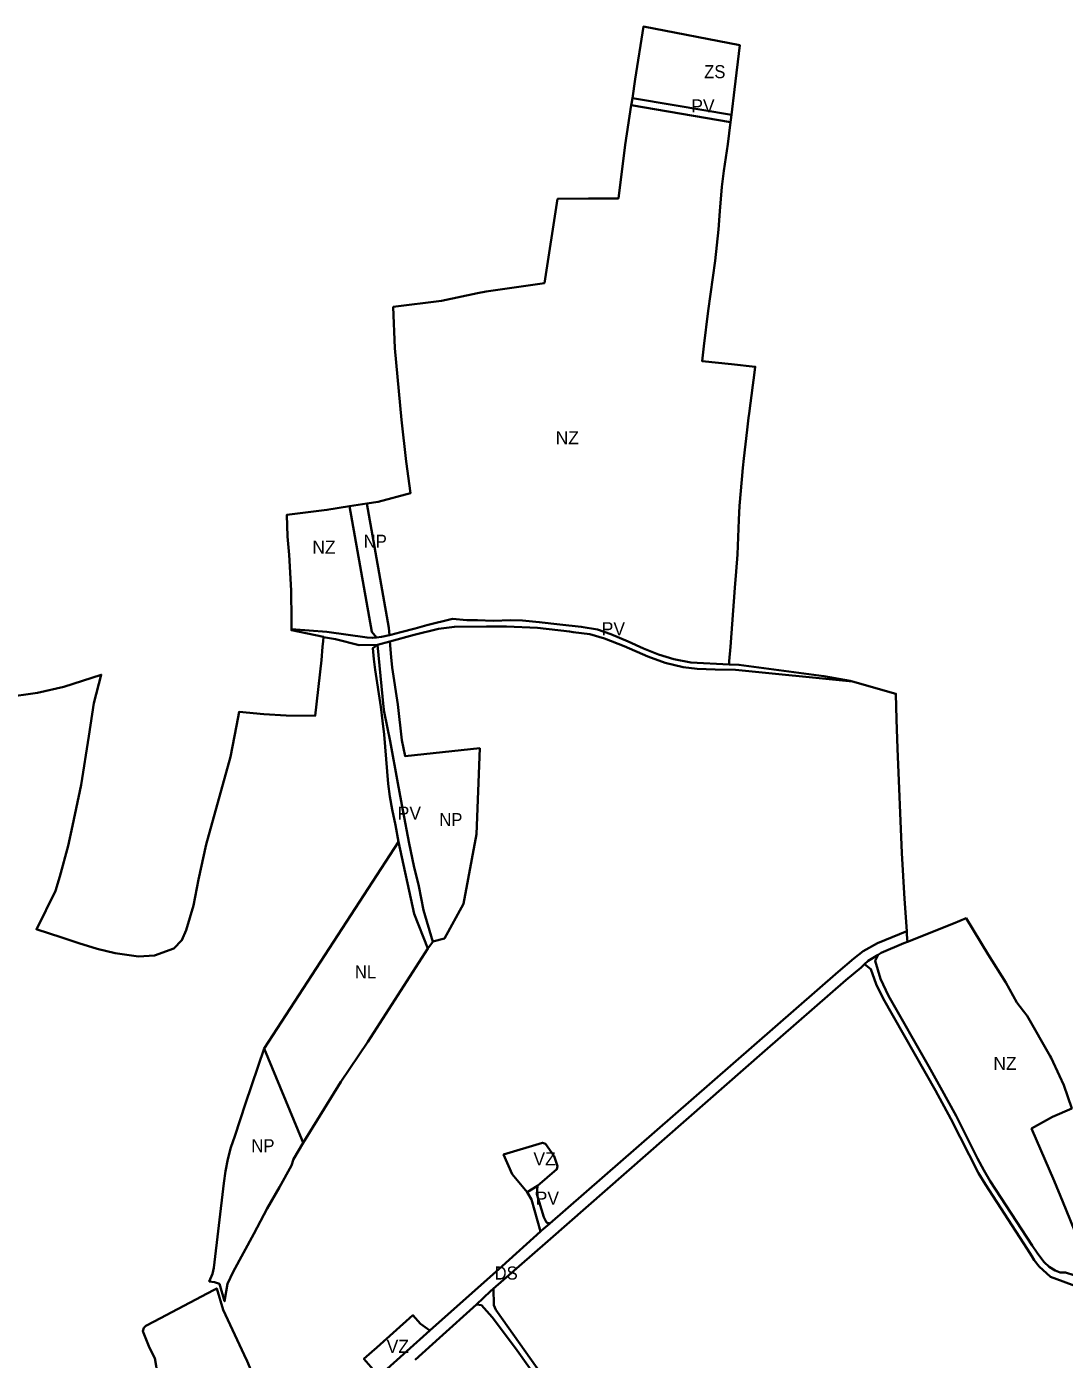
# Model space of a CAD drawing. Extents: x -650451 to -642268, y -1075216 to -1066610.
# Drawn here: x -646190 to -644999, y -1068487 to -1066957 of the extents above; entities that cross this region are included whole.
import ezdxf

# ---------------------------------------------------------------- set-up
doc = ezdxf.new("R2010")
doc.units = 0
doc.header["$LTSCALE"] = 6
doc.layers.add('1', color=7, linetype='Continuous', lineweight=35)
doc.layers.add('2', color=7, linetype='Continuous')
doc.layers.add('3', color=7, linetype='Continuous')

msp = doc.modelspace()

# ---------------------------------------------------------------- linework, layer by layer
at = {"layer": '1'}
for p, q in [((-645382.21, -1067066.58), (-645496.09, -1067047.12)), ((-645799.72, -1067504.47), (-645819.48, -1067507.57)), ((-645787.55, -1067666.46), (-645773.23, -1067662.67)), ((-645917.44, -1068129.99), (-645763.31, -1067892.76)), ((-645729.57, -1068015.25), (-645723.73, -1068007.49)), ((-645603.62, -1068287.78), (-645615.49, -1068294.75)), ((-645657.63, -1068408.53), (-645673.86, -1068423.84))]:
    msp.add_line(p, q, dxfattribs=at)
for points in [[(-645494.89, -1067039.24), (-645491.53, -1067017.12), (-645482.19, -1066956.97), (-645371.52, -1066978.24), (-645377.46, -1067029.23), (-645381.13, -1067058.07)], [(-645494.89, -1067039.24), (-645495.83, -1067045.42), (-645495.92, -1067046), (-645496.09, -1067047.12)], [(-645381.13, -1067058.07), (-645446.75, -1067047.21), (-645494.89, -1067039.24)], [(-645496.09, -1067047.12), (-645503.12, -1067092.52), (-645510.95, -1067154.14), (-645545.1, -1067154.42), (-645580.79, -1067154.71), (-645595.88, -1067251.4), (-645662.58, -1067260.94), (-645672.62, -1067263.07), (-645713.88, -1067271.8), (-645769.39, -1067278.68), (-645767.6, -1067326), (-645759.82, -1067408.4), (-645754.45, -1067456.07), (-645749.67, -1067492.54), (-645786.52, -1067502.4), (-645799.72, -1067504.47)], [(-645383.93, -1067689.29), (-645383.61, -1067685.21), (-645382.36, -1067669.07), (-645377.07, -1067601.06), (-645375.63, -1067582.48), (-645374.09, -1067562.75), (-645372.51, -1067523.27), (-645371.73, -1067507.06), (-645369.16, -1067476.7), (-645367.93, -1067463.58), (-645366.91, -1067452.72), (-645363.1, -1067419.95), (-645361.48, -1067406.06), (-645360.9, -1067401.05), (-645356.48, -1067368.37), (-645354.97, -1067357.16), (-645353.76, -1067347.31), (-645381.01, -1067344.47), (-645414.55, -1067340.98), (-645412.77, -1067323.6), (-645407.69, -1067283.25), (-645399.81, -1067225.64), (-645395.86, -1067189.95), (-645394.32, -1067168.93), (-645392.26, -1067140.66), (-645389.77, -1067122.54), (-645385.41, -1067091.78), (-645382.21, -1067066.58)], [(-645382.21, -1067066.58), (-645381.88, -1067064.01), (-645381.13, -1067058.07)], [(-645819.48, -1067507.57), (-645845.49, -1067511.66), (-645891.61, -1067517.46), (-645890.8, -1067542.09), (-645888.69, -1067563.35), (-645886.5, -1067604.41), (-645886.3, -1067638), (-645886.24, -1067648.47)], [(-645819.48, -1067507.57), (-645793.94, -1067651.61), (-645788.395, -1067658.038)], [(-645799.72, -1067504.47), (-645774.48, -1067646.99), (-645773.771, -1067655.463)], [(-645383.93, -1067689.29), (-645427.67, -1067686.98), (-645447.36, -1067682.99), (-645464.97, -1067677.86), (-645481.91, -1067670.72), (-645499.63, -1067662.69), (-645519.72, -1067654.33), (-645534.71, -1067649.04), (-645553.5, -1067645.77), (-645578.23, -1067643.18), (-645601.76, -1067640.56), (-645621.09, -1067638.61), (-645634.35, -1067638.25), (-645654.82, -1067638.96), (-645672.81, -1067638.43), (-645685.05, -1067638.32), (-645701.45, -1067636.93), (-645730.83, -1067643.84), (-645744.22, -1067647.86), (-645760.67, -1067652.05), (-645772.13, -1067655.13), (-645773.771, -1067655.463)], [(-645886.24, -1067648.47), (-645886.23, -1067649.44), (-645886.23, -1067649.94), (-645849.48, -1067657.36), (-645849.52, -1067657.86)], [(-645886.24, -1067648.47), (-645845.57, -1067651.64), (-645799.46, -1067658.29), (-645792.97, -1067658.65), (-645788.395, -1067658.038)], [(-645773.23, -1067662.67), (-645745.35, -1067655.28), (-645717.47, -1067648.33), (-645699.06, -1067645.85), (-645662.28, -1067645.47), (-645639.18, -1067645.44), (-645603.9, -1067647.11), (-645566.95, -1067651.44), (-645562.8, -1067651.97), (-645543.71, -1067654.42), (-645526.79, -1067659.39), (-645504.22, -1067668.01), (-645477.15, -1067680.1), (-645457.35, -1067687.14), (-645436.45, -1067692.2), (-645420.53, -1067694.05), (-645399.68, -1067695), (-645376.45, -1067695.27), (-645241.99, -1067708.63)], [(-645849.52, -1067657.86), (-645849.92, -1067662.49), (-645850.48, -1067668.94), (-645851.81, -1067684.35), (-645858.82, -1067747.99), (-645892.22, -1067747.76), (-645917.73, -1067746.17), (-645946.03, -1067743.35), (-645949.27, -1067759.64), (-645955.97, -1067795.26), (-645983.9, -1067895.9), (-645992.8, -1067935.9), (-645998.8, -1067965.7), (-646007, -1067994.3), (-646011.9, -1068005.55), (-646021.3, -1068015.1), (-646043.5, -1068023.3), (-646061.9, -1068024.2), (-646088.7, -1068020.6), (-646109.2, -1068015.7), (-646130.17, -1068008.93), (-646151, -1068002.21), (-646178.1, -1067993.46), (-646178.9, -1067993.2), (-646157.138, -1067949.001), (-646152.186, -1067932.667), (-646142.3, -1067897.5), (-646137.4, -1067874.3), (-646127.7, -1067827.4), (-646118.8, -1067771.3), (-646113, -1067733.4), (-646104.6, -1067701), (-646147.4, -1067714.8), (-646177.7, -1067721.6), (-646215.6, -1067727)], [(-645849.52, -1067657.86), (-645835.71, -1067660.17), (-645808.36, -1067666.89), (-645787.55, -1067666.46)], [(-645763.31, -1067892.76), (-645766.73, -1067873.61), (-645770.55, -1067855.68), (-645773.28, -1067840.65), (-645775.01, -1067826.23), (-645779.93, -1067769.7), (-645781.58, -1067753.73), (-645783.74, -1067737.82), (-645790.2, -1067695.38), (-645791.77, -1067682.92), (-645792.71, -1067670.4), (-645787.55, -1067666.46)], [(-645788.395, -1067658.038), (-645782.72, -1067657.28), (-645773.771, -1067655.463)], [(-645787.55, -1067666.46), (-645780.39, -1067737.84), (-645779.64, -1067743.41), (-645773.04, -1067777.35), (-645764.11, -1067825.26), (-645758.47, -1067856.55), (-645751.08, -1067894.5), (-645745.86, -1067920.32), (-645739.85, -1067943.75), (-645734.61, -1067971.28), (-645723.73, -1068007.49)], [(-645773.23, -1067662.67), (-645771.86, -1067680.92), (-645770.39, -1067692.63), (-645763.92, -1067735.14), (-645759.32, -1067775.89), (-645755.758, -1067794.254), (-645670.064, -1067785.335), (-645673.827, -1067884.119), (-645688.88, -1067964.087), (-645710.519, -1068003.601), (-645723.785, -1068007.069), (-645723.73, -1068007.49)], [(-645241.99, -1067708.63), (-645244.7, -1067707.86), (-645275.06, -1067702.69), (-645372.48, -1067689.42), (-645383.93, -1067689.29)], [(-645179.89, -1067995.2), (-645182.4, -1067958.11), (-645185.5, -1067905.76), (-645190.61, -1067785.41), (-645191.55, -1067752.42), (-645192.4, -1067722.74), (-645241.99, -1067708.63)], [(-645763.31, -1067892.76), (-645745.28, -1067975.27), (-645729.57, -1068015.25)], [(-644959.42, -1068409.51), (-644963.44, -1068401.84), (-644969.23, -1068390.78), (-644983.04, -1068349.19), (-645000.93, -1068306.11), (-645010.65, -1068282), (-645036.69, -1068221.92), (-645012.64, -1068208.23), (-644990.43, -1068198.75), (-644999.74, -1068171.88), (-645004.64, -1068161.3), (-645014.09, -1068140.85), (-645015.38, -1068138.59), (-645041.75, -1068092.48), (-645045.78, -1068087.19), (-645053.36, -1068077.25), (-645066.21, -1068054.16), (-645086.3, -1068021.92), (-645111.83, -1067980.38), (-645126.11, -1067986.52), (-645179.06, -1068007.39)], [(-645589.734, -1068330.849), (-645427.4, -1068189.15), (-645258.58, -1068041.8), (-645240.62, -1068026.53), (-645229.95, -1068018.28), (-645213.6, -1068009.2), (-645179.89, -1067995.2)], [(-645179.89, -1067995.2), (-645179.67, -1067998.38), (-645179.28, -1068004.08), (-645179.06, -1068007.39)], [(-645729.57, -1068015.25), (-645798.69, -1068122.17), (-645829.66, -1068168.34), (-645872.64, -1068238.08)], [(-645179.06, -1068007.39), (-645183.06, -1068008.96), (-645209.31, -1068020.07), (-645212.831, -1068022.262)], [(-645228.257, -1068033.102), (-645232.31, -1068036.91), (-645249.9, -1068051.45), (-645342.79, -1068132.81), (-645592.08, -1068351.12), (-645657.63, -1068408.53)], [(-645212.831, -1068022.262), (-645224.36, -1068029.44), (-645228.257, -1068033.102)], [(-644982.58, -1068403.83), (-645014.95, -1068392.17), (-645027.82, -1068380.21), (-645033.49, -1068372.96), (-645036.31, -1068368.47), (-645041.56, -1068359.96), (-645089.68, -1068286.16), (-645097.68, -1068273.03), (-645129.48, -1068210.55), (-645147.09, -1068178.35), (-645206.9, -1068072.73), (-645215.02, -1068056.12), (-645221, -1068038.9), (-645228.257, -1068033.102)], [(-644959.42, -1068409.51), (-644966.17, -1068403.25), (-644970.72, -1068399.33), (-644978.39, -1068393.26), (-644997.7, -1068387.1), (-645003.98, -1068387.18), (-645009.72, -1068384.69), (-645016.44, -1068380.44), (-645022.34, -1068375.11), (-645027.23, -1068368.85), (-645030.2, -1068364.48), (-645035.86, -1068356.25), (-645083.99, -1068282.08), (-645091.6, -1068269.57), (-645098.61, -1068256.33), (-645106.55, -1068240.15), (-645123.29, -1068207.28), (-645140.99, -1068174.92), (-645154.68, -1068150.75), (-645200.78, -1068069.33), (-645210.19, -1068049.9), (-645216.33, -1068029.45), (-645212.831, -1068022.262)], [(-645917.44, -1068129.99), (-645938.87, -1068193.06), (-645951.35, -1068230.61), (-645955.63, -1068243.79), (-645959.15, -1068257.17), (-645961.93, -1068270.74), (-645963.94, -1068284.44), (-645975.46, -1068381.74), (-645976.72, -1068388.53), (-645980.61, -1068397.35), (-645974.67, -1068398.28), (-645968.86, -1068400.15), (-645962.86, -1068420.15), (-645959.41, -1068400.16), (-645952.92, -1068386.53), (-645929.29, -1068342.91), (-645914.12, -1068313.54), (-645899.73, -1068289.25), (-645886.28, -1068264.22), (-645883.87, -1068256.88), (-645872.64, -1068238.08)], [(-645872.64, -1068238.08), (-645874.15, -1068234.44), (-645917.44, -1068129.99)], [(-645615.49, -1068294.75), (-645632.7, -1068274.33), (-645642.71, -1068251.69), (-645597.95, -1068238.07), (-645594.58, -1068239.29), (-645584.8, -1068253.71), (-645580.86, -1068265.06), (-645581.51, -1068268.4), (-645603.62, -1068287.78)], [(-645600.441, -1068340.017), (-645610.72, -1068303.48), (-645615.49, -1068294.75)], [(-645603.62, -1068287.78), (-645604.65, -1068297.22), (-645596.36, -1068323.47), (-645593.42, -1068329.62), (-645589.734, -1068330.849)], [(-645727.32, -1068453.86), (-645644.17, -1068379.88), (-645600.441, -1068340.017)], [(-645600.441, -1068340.017), (-645599.6, -1068339.25), (-645596.883, -1068336.974), (-645590.025, -1068331.103), (-645589.734, -1068330.849)], [(-646149.04, -1068659.6), (-646149.99, -1068658.12), (-646136.66, -1068651.17), (-646028.19, -1068584.65), (-646036.27, -1068530.56), (-646041.44, -1068494.27), (-646043.13, -1068485.53), (-646048.96, -1068473.76), (-646051.28, -1068467.73), (-646055.39, -1068458.11), (-646056.77, -1068454.35), (-646055.56, -1068450.55), (-646053.26, -1068448.37), (-646043.93, -1068443.44), (-645975.47, -1068407.25), (-645971.94, -1068405.38), (-645964.53, -1068429.83), (-645964.51, -1068429.88), (-645940.28, -1068481.66), (-645936.95, -1068488.76), (-645927.86, -1068510.76), (-645924.25, -1068530.17), (-645922.02, -1068539.96)], [(-645657.63, -1068408.53), (-645654.34, -1068405.65), (-645653.87, -1068424.71), (-645651.53, -1068430.1), (-645591.03, -1068515.22), (-645587.94, -1068519.19), (-645580.2, -1068531.93), (-645576.6, -1068540.35), (-645574.36, -1068545.66), (-645570.55, -1068560.09), (-645568.86, -1068574.89), (-645568.88, -1068579.93), (-645563.42, -1068709.35), (-645557.97, -1068838.77), (-645557.27, -1068843.66), (-645556.12, -1068850.33), (-645553.29, -1068856.55), (-645552.302, -1068859.444)], [(-645673.86, -1068423.84), (-645716.22, -1068462.08), (-645744.06, -1068487.4)], [(-645632.76, -1068904.96), (-645605.99, -1068885.11), (-645567.83, -1068857.79), (-645564.25, -1068849.99), (-645565.26, -1068844.12), (-645564.97, -1068839.07), (-645565.34, -1068825.58), (-645568.99, -1068739.04), (-645571.75, -1068677.77), (-645575.86, -1068580.22), (-645576.29, -1068575.28), (-645577.8, -1068561.45), (-645581.4, -1068548.08), (-645586.82, -1068535.33), (-645594.04, -1068523.44), (-645596.74, -1068519.27), (-645628.94, -1068473.97), (-645655.81, -1068438.19), (-645668.04, -1068424.72), (-645673.86, -1068423.84)], [(-645727.32, -1068453.86), (-645737.89, -1068446.04), (-645746.68, -1068436.15), (-645788.09, -1068473.04), (-645794.06, -1068478.36), (-645803.01, -1068486.33), (-645789.58, -1068501.42)], [(-645727.32, -1068453.86), (-645780.28, -1068501.04), (-645785.72, -1068505.75)]]:
    msp.add_lwpolyline(points, dxfattribs=at)

# ---------------------------------------------------------------- texts
at = {"layer": '2', "width": 0.95}
for s, p in [('ZS', (-645412.41, -1067016.14)), ('NL', (-645813.379, -1068049.487)), ('DS', (-645652.946, -1068395.219))]:
    msp.add_text(s, height=15, dxfattribs=at).set_placement(p)
at = {"layer": '2'}
for s, p in [('PV', (-645427.21, -1067055.413)), ('NZ', (-645582.923, -1067436.348)), ('NZ', (-645862.221, -1067561.959)), ('PV', (-645530.032, -1067655.666)), ('PV', (-645764.204, -1067867.241)), ('NZ', (-645080.481, -1068154.543)), ('VZ', (-645608.45, -1068264.15)), ('PV', (-645605.805, -1068309.279)), ('VZ', (-645776.91, -1068479.37))]:
    msp.add_text(s, height=15, dxfattribs=at).set_placement(p)
at = {"layer": '3', "width": 0.95}
for p in [(-645803.164, -1067555.233), (-645716.434, -1067874.728), (-645932.149, -1068249.079)]:
    msp.add_text('NP', height=15, dxfattribs=at).set_placement(p)

doc.saveas('drawing.dxf')
